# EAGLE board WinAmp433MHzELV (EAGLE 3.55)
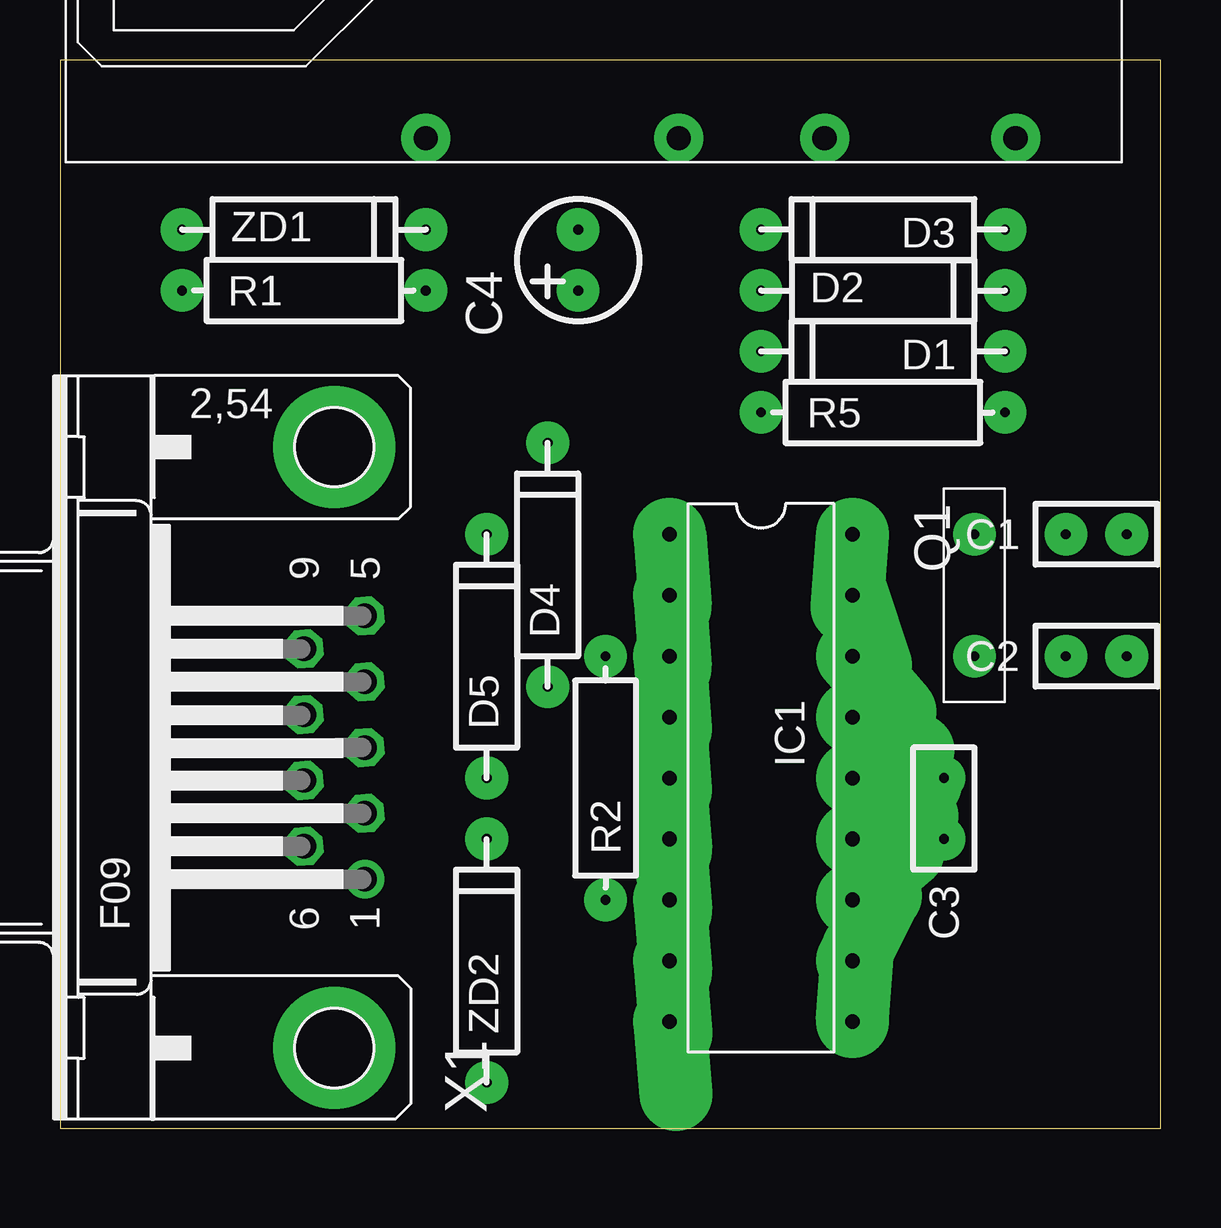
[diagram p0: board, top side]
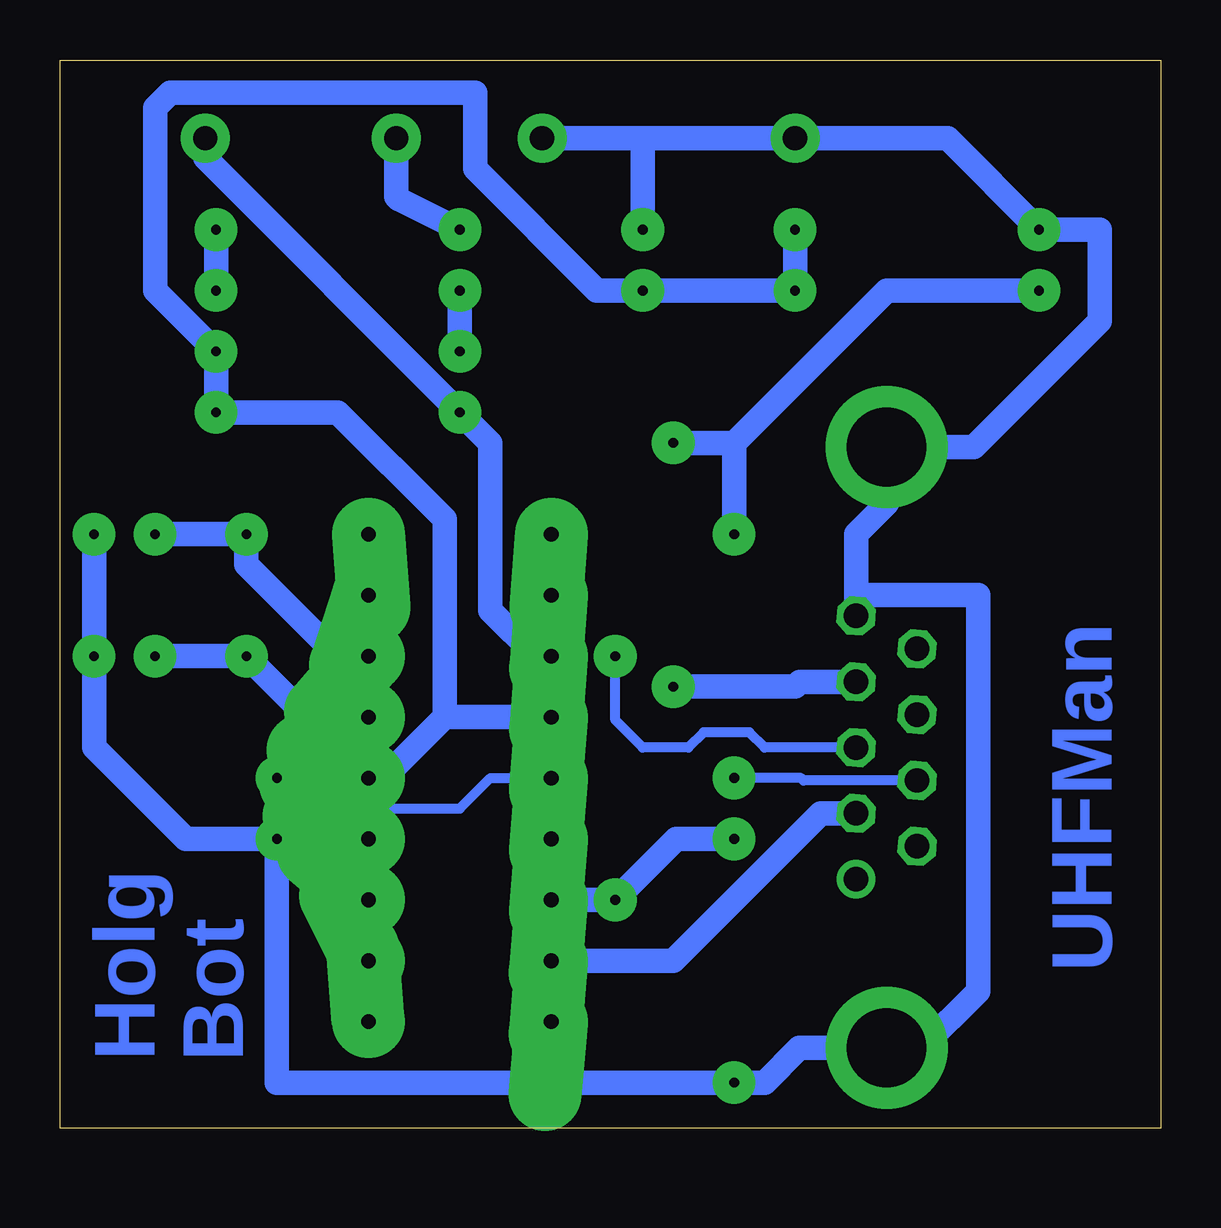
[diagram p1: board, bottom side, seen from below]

Size 45.87 x 44.53 mm. Coordinates in mm from the lower left corner, seen from the top.
Outline: 0,0 45.87,0 45.87,44.53 0,44.53 0,0
Copper layers used: Bottom

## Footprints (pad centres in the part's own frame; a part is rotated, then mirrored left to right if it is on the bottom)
RM2,5 = drill 0.406 pad 1.778 round:  0,0;  2.54,0
KO01 = drill 0.406 pad 1.778 round:  0,0;  2.54,0
O04 = drill 0.406 pad 1.778 round:  0,0;  10.16,0
L-18B = drill 0.61 pad 3.048 offset:  0,0;  2.54,0;  15.24,0;  17.78,0;  5.08,0;  7.62,0;  12.7,0;  10.16,0;  20.32,0;  20.32,7.62;  17.78,7.62;  15.24,7.62;  12.7,7.62;  10.16,7.62;  7.62,7.62;  5.08,7.62;  2.54,7.62;  0,7.62
V433RE = drill 1.016 pad 2.032 round: 1 10.54,0; OD 24.58,0;  0,0;  16.62,0
ARZ_ST = drill 0.406 pad 1.778 round:  0,0;  5.08,0
S04 = drill 0.406 pad 1.778 round:  0,0;  10.16,0
9HP = drill 1.016 pad 1.6 round:  -5.486,-1.27 | drill 1.016 pad 1.6 octagon:  -2.743,-1.27;  0,-1.27;  2.743,-1.27;  5.486,-1.27;  -4.115,1.27;  -1.372,1.27;  1.372,1.27;  4.115,1.27 | drill 3.302 pad 5.08 round:  -12.522,0;  12.522,0

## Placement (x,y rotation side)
C1  27p  [RM2,5]  44.45,24.77 180 top
C2  27p  [RM2,5]  44.45,19.68 180 top
C3  C100NK  [RM2,5]  36.83,14.61 270 top
C4  4u7  [KO01]  21.59,34.92 90 top
D1  1N4148  [O04]  39.37,32.38 180 top
D2  1N4148  [O04]  29.21,34.92 0 top
D3  1N4148  [O04]  39.37,37.47 180 top
D4  1N4148  [O04]  20.32,18.41 90 top
D5  1N4148  [O04]  17.78,14.61 90 top
IC1  16F84P  [L-18B]  25.4,24.77 270 top
M1  ELV433REC  [V433RE]  15.24,41.27 0 top
Q1  4MHz  [ARZ_ST]  38.1,24.77 270 top
R1  1k  [S04]  5.08,34.92 0 top
R2  33k  [S04]  22.73,9.53 90 top
R5  47k  [S04]  29.21,29.84 0 top
X1  F09HP  [9HP]  11.43,15.88 90 top
ZD1  5V1  [O04]  5.08,37.47 0 top
ZD2  5V1  [O04]  17.78,1.91 90 top

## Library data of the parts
C1-C4 D1-D5 IC1 Q1 R1 R2 R5 ZD1 ZD2 = holg_plt
M1 = ic_holg3
X1 = SUBD-A

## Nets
+5V: C3. C4. D1. IC1. R1. R5. ZD1.
GND: C1. C2. C3. C4. IC1. M1. M1.1 X1. ZD1. ZD2.
N$1: C1. IC1. Q1.
N$2: C2. IC1. Q1.
N$3: D4. X1.
N$4: D5. X1.
N$5: D4. D5. R1.
N$6: IC1. R2. ZD2.
N$8: R2. X1.
N$9: IC1. X1.
N$15: IC1. M1.OD R5.
N$16: D1. D2.
N$17: D2. D3.
N$18: D3. M1.

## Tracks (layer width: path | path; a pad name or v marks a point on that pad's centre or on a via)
+5V
  Bottom 1.016: 36.83,14.61 33.02,14.61 32.38,14.61 29.84,17.14 | ZD1. R1. 21.59,34.92 23.5,34.92 28.57,40.01 28.57,43.18 41.27,43.18 41.91,42.55 41.91,34.92 39.37,32.38 R5. 34.29,29.84 29.84,25.4 29.84,17.14 | 25.4,17.14 29.84,17.14
GND
  Bottom 0.406: C3. 35.56,13.34 29.21,13.34 27.94,14.61 25.4,14.61
  Bottom 1.016: 21.59,41.27 15.24,41.27 8.89,41.27 5.08,37.47 2.54,37.47 2.54,33.66 7.8,28.4 X1. 11.43,26.04 12.7,24.77 12.7,22.23 | 21.59,41.27 M1.1 | 44.45,24.77 44.45,19.68 44.45,15.88 40.64,12.06 C3. 36.83,1.91 17.78,1.91 16.51,1.91 15.06,3.35 11.43,3.35 9.98,3.35 7.62,5.71 7.62,22.23 12.7,22.23 | 12.7,22.23 12.7,21.36 | 21.59,41.27 C4.
N$1
  Bottom 1.016: 33.02,19.68 34.29,19.68 38.1,23.5 38.1,24.77 C1.
N$2
  Bottom 1.016: 33.02,17.14 35.56,17.14 Q1. C2.
N$3
  Bottom 1.016: 12.7,18.62 15.04,18.62 15.24,18.41 20.32,18.41
N$4
  Bottom 0.406: 10.16,14.5 14.88,14.5 14.99,14.61 17.78,14.61
N$5
  Bottom 1.016: 17.78,28.57 D5. | 5.08,34.92 11.43,34.92 17.78,28.57 | 17.78,28.57 D4.
N$6
  Bottom 1.016: 25.4,9.53 22.73,9.53 20.19,12.06 ZD2.
N$8
  Bottom 0.406: 12.7,15.88 16.51,15.88 17.14,16.51 19.05,16.51 19.68,15.88 21.59,15.88 22.73,17.02 R2.
N$9
  Bottom 1.016: 12.7,13.13 14.17,13.13 20.32,6.99 25.4,6.99
N$15
  Bottom 0.406: 25.4,19.68 26.04,19.68
  Bottom 1.016: M1.OD 39.82,40.45 29.21,29.84 27.94,28.57 27.94,21.59 26.04,19.68
N$16
  Bottom 1.016: D1. 29.21,34.92
N$17
  Bottom 1.016: D2. 39.37,37.47
N$18
  Bottom 0.406: 31.86,38.73 31.75,38.73 31.86,38.84
  Bottom 1.016: D3. 31.75,38.73 | 31.86,38.84 M1.

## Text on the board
Bottom: UHFMan | Holg | Bot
